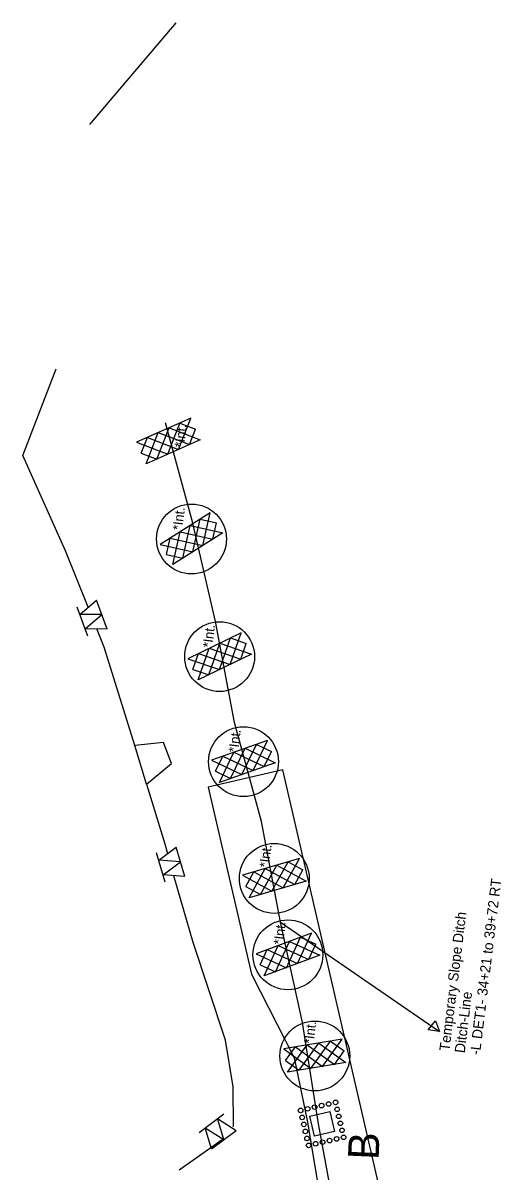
# Model space of a CAD drawing. Extents: x 400935 to 481562, y 415700 to 505362.
# Drawn here: x 481162 to 481396, y 491893 to 492453 of the extents above; entities that cross this region are included whole.
import ezdxf

# ---------------------------------------------------------------- set-up
doc = ezdxf.new("R2010")
doc.units = 0
for name, color, linetype in [('303d Impaired Stream Note CELL', 7, 'Continuous'), ('Label B Final CELL', 7, 'Continuous'), ('Old_Level_2', 7, 'Continuous'), ('Rock Inlet Sediment Trap Type B Final CELL', 7, 'Continuous'), ('Scratch_Level_3', 7, 'Continuous'), ('Scratch_Level_4', 7, 'Continuous'), ('Special Sediment Control Fence Section Both CELL', 7, 'Continuous'), ('Temporary Silt Fence Both', 7, 'Continuous'), ('Temporary Silt Fence CG', 7, 'Continuous'), ('Temporary Silt Fence Final', 7, 'Continuous')]:
    doc.layers.add(name, color=color, linetype=linetype)

msp = doc.modelspace()

# ---------------------------------------------------------------- linework, layer by layer
at = {"layer": '303d Impaired Stream Note CELL'}
msp.add_line((481194.94, 492403.56), (481237.1, 492453.11), dxfattribs=at)
at = {"layer": 'Old_Level_2'}
for p, q in [((481244.14, 492260.32), (481217.7, 492248.65)), ((481238.24, 492245.09), (481244.14, 492260.32)), ((481227.68, 492240.42), (481233.58, 492255.66)), ((481232.94, 492242.75), (481238.88, 492258)), ((481233.58, 492255.66), (481248.81, 492249.76)), ((481238.88, 492258), (481246.5, 492255.02)), ((481243.57, 492247.5), (481246.5, 492255.02)), ((481217.7, 492248.65), (481232.94, 492242.75)), ((481220.04, 492243.34), (481223.01, 492251)), ((481222.37, 492238.09), (481228.27, 492253.32)), ((481248.81, 492249.76), (481222.37, 492238.09)), ((481223.01, 492251), (481238.24, 492245.09)), ((481228.27, 492253.32), (481243.55, 492247.44)), ((481220.04, 492243.34), (481227.68, 492240.42)), ((481253.61, 492214.18), (481229.21, 492198.69)), ((481245.15, 492195.13), (481248.75, 492211.1)), ((481248.75, 492211.1), (481256.72, 492209.29)), ((481250.04, 492198.24), (481253.61, 492214.18)), ((481235.39, 492188.94), (481238.96, 492204.88)), ((481259.79, 492204.43), (481235.39, 492188.94)), ((481238.96, 492204.88), (481254.94, 492201.35)), ((481240.3, 492192.04), (481243.85, 492207.99)), ((481243.85, 492207.99), (481259.79, 492204.43)), ((481254.96, 492201.42), (481256.72, 492209.29)), ((481229.21, 492198.69), (481245.15, 492195.13)), ((481232.3, 492193.79), (481234.1, 492201.8)), ((481234.1, 492201.8), (481250.04, 492198.24)), ((481232.3, 492193.79), (481240.3, 492192.04)), ((481268.69, 492155.71), (481242.7, 492143.06)), ((481263.36, 492140.27), (481268.69, 492155.71)), ((481247.75, 492132.68), (481253.09, 492148.12)), ((481252.98, 492135.2), (481258.3, 492150.66)), ((481253.09, 492148.12), (481268.57, 492142.81)), ((481258.14, 492137.73), (481263.52, 492153.19)), ((481258.3, 492150.66), (481273.74, 492145.33)), ((481263.52, 492153.19), (481271.24, 492150.5)), ((481268.59, 492142.88), (481271.24, 492150.5)), ((481242.7, 492143.06), (481258.14, 492137.73)), ((481245.23, 492137.84), (481247.92, 492145.6)), ((481273.74, 492145.33), (481247.75, 492132.68)), ((481247.92, 492145.6), (481263.36, 492140.27)), ((481245.23, 492137.84), (481252.98, 492135.2)), ((481281.61, 492103.19), (481254.34, 492093.61)), ((481274.54, 492088.46), (481281.61, 492103.19)), ((481263.64, 492084.63), (481270.71, 492099.36)), ((481269.06, 492086.54), (481276.18, 492101.28)), ((481270.71, 492099.36), (481285.43, 492092.29)), ((481276.18, 492101.28), (481283.54, 492097.72)), ((481280.04, 492090.45), (481283.54, 492097.72)), ((481254.34, 492093.61), (481269.06, 492086.54)), ((481256.25, 492088.14), (481259.81, 492095.53)), ((481258.17, 492082.72), (481265.24, 492097.44)), ((481285.43, 492092.29), (481258.17, 492082.72)), ((481259.81, 492095.53), (481274.54, 492088.46)), ((481265.24, 492097.44), (481280.01, 492090.39)), ((481256.25, 492088.14), (481263.64, 492084.63)), ((481297.18, 492045.62), (481269.44, 492037.51)), ((481278.25, 492028.04), (481286.09, 492042.38)), ((481283.76, 492029.66), (481291.66, 492044)), ((481286.09, 492042.38), (481300.42, 492034.53)), ((481289.33, 492031.29), (481297.18, 492045.62)), ((481291.66, 492044), (481298.82, 492040.05)), ((481269.44, 492037.51), (481283.76, 492029.66)), ((481271.05, 492031.94), (481275.01, 492039.14)), ((481272.68, 492026.42), (481280.52, 492040.75)), ((481275.01, 492039.14), (481289.33, 492031.29)), ((481280.52, 492040.75), (481294.9, 492032.92)), ((481294.93, 492032.98), (481298.82, 492040.05)), ((481271.05, 492031.94), (481278.25, 492028.04)), ((481300.42, 492034.53), (481272.68, 492026.42)), ((481303.1, 492009.22), (481276.01, 491999.16)), ((481296.3, 491994.37), (481303.1, 492009.22)), ((481280.03, 491988.33), (481286.84, 492003.18)), ((481285.47, 491990.34), (481292.27, 492005.2)), ((481286.84, 492003.18), (481301.73, 491996.39)), ((481290.86, 491992.35), (481297.71, 492007.22)), ((481292.27, 492005.2), (481307.12, 491998.39)), ((481297.71, 492007.22), (481305.13, 492003.79)), ((481301.76, 491996.46), (481305.13, 492003.79)), ((481276.01, 491999.16), (481290.86, 491992.35)), ((481278.02, 491993.72), (481281.45, 492001.18)), ((481307.12, 491998.39), (481280.03, 491988.33)), ((481281.45, 492001.18), (481296.3, 491994.37)), ((481278.02, 491993.72), (481285.47, 491990.34)), ((481318.03, 491957.48), (481289.52, 491952.78)), ((481289.52, 491952.78), (481302.8, 491943.26)), ((481290.45, 491947.05), (481295.24, 491953.72)), ((481291.4, 491941.38), (481300.92, 491954.66)), ((481295.24, 491953.72), (481308.52, 491944.2)), ((481297.12, 491942.31), (481306.64, 491955.6)), ((481300.92, 491954.66), (481314.24, 491945.15)), ((481302.8, 491943.26), (481312.36, 491956.54)), ((481306.64, 491955.6), (481319.91, 491946.08)), ((481308.52, 491944.2), (481318.03, 491957.48)), ((481312.36, 491956.54), (481318.99, 491951.76)), ((481290.45, 491947.05), (481297.12, 491942.31)), ((481314.28, 491945.2), (481318.99, 491951.76)), ((481319.91, 491946.08), (481291.4, 491941.38))]:
    msp.add_line(p, q, dxfattribs=at)
for centre in [(481244.53, 492201.43), (481258.24, 492144.06), (481269.89, 492092.82), (481284.92, 492035.89), (481291.57, 491998.64), (481304.7, 491949.3)]:
    msp.add_circle(centre, 17.04, dxfattribs=at)
at = {"layer": 'Rock Inlet Sediment Trap Type B Final CELL'}
msp.add_lwpolyline([(481304.5, 491910.19), (481302.26, 491919.94), (481312.01, 491922.18), (481314.24, 491912.43)], close=True, dxfattribs=at)
for centre in [(481301.17, 491923.53), (481304.58, 491924.31), (481307.99, 491925.1), (481311.41, 491925.88), (481314.82, 491926.66), (481315.6, 491923.25), (481297.76, 491922.75), (481298.54, 491919.34), (481316.38, 491919.84), (481299.33, 491915.93), (481300.11, 491912.51), (481317.17, 491916.43), (481317.95, 491913.02), (481300.89, 491909.1), (481305.09, 491906.47), (481308.5, 491907.26), (481311.91, 491908.04), (481315.32, 491908.82), (481318.73, 491909.61), (481301.67, 491905.69)]:
    msp.add_circle(centre, 1.12, dxfattribs=at)
at = {"layer": 'Scratch_Level_3'}
for points in [[(481355.37, 491722.18), (481334.07, 491768.58), (481324.82, 491817.76), (481315.61, 491866.95), (481306.43, 491916.15), (481298.76, 491965.69), (481287.96, 492014.51), (481278.67, 492063.68), (481265.49, 492111.96), (481256.21, 492161.13), (481244.98, 492209.85), (481231.8, 492258.12)], [(481287.96, 492014.51), (481365.59, 491961.24), (481360.01, 491962.07), (481363.61, 491966.44), (481365.59, 491961.24)]]:
    msp.add_lwpolyline(points, dxfattribs=at)
at = {"layer": 'Scratch_Level_4'}
msp.add_lwpolyline([(481332.89, 491715.21), (481374.23, 491721.13), (481289.04, 492088.86), (481252.67, 492080.43), (481273.82, 491989.14), (481294.57, 491948.38), (481300.91, 491917.87), (481325.82, 491768.95)], close=True, dxfattribs=at)
at = {"layer": 'Special Sediment Control Fence Section Both CELL'}
for p, q in [((481203.3, 492157.52), (481198.18, 492171.62)), ((481193.9, 492154.11), (481188.78, 492168.21)), ((481231.69, 492033.99), (481227.48, 492048.38)), ((481241.29, 492036.8), (481237.07, 492051.19)), ((481248.26, 491911.98), (481260.24, 491921.01)), ((481254.27, 491903.99), (481266.25, 491913.02))]:
    msp.add_line(p, q, dxfattribs=at)
for points in [[(481200.74, 492164.57), (481190.06, 492164.68), (481198.18, 492171.62)], [(481203.3, 492157.52), (481192.62, 492157.63), (481200.74, 492164.57)], [(481239.18, 492044), (481228.53, 492044.79), (481237.07, 492051.19)], [(481241.29, 492036.8), (481230.64, 492037.59), (481239.18, 492044)], [(481260.26, 491908.51), (481257.24, 491918.75), (481266.25, 491913.02)], [(481254.27, 491903.99), (481251.25, 491914.24), (481260.26, 491908.51)]]:
    msp.add_lwpolyline(points, dxfattribs=at)
at = {"layer": 'Temporary Silt Fence Both'}
msp.add_line((481238.59, 491893.81), (481259.43, 491908.57), dxfattribs=at)
for points in [[(481194.07, 492168.11), (481183.06, 492195.58), (481162.29, 492242.1), (481178.5, 492284.48)], [(481216.83, 492100.74), (481201.89, 492148.61), (481198.29, 492157.58)], [(481222.59, 492081.83), (481231.44, 492052.79), (481232.82, 492048)], [(481265, 491914.72), (481264.87, 491934.28), (481261.19, 491957.03), (481245.3, 492004.68), (481235.93, 492037.2)]]:
    msp.add_lwpolyline(points, dxfattribs=at)
at = {"layer": 'Temporary Silt Fence CG'}
msp.add_lwpolyline([(481222.59, 492081.83), (481234.79, 492091.9), (481230.84, 492102.24), (481216.83, 492100.74)], dxfattribs=at)
at = {"layer": 'Temporary Silt Fence Final'}
msp.add_line((481222.59, 492081.83), (481216.83, 492100.74), dxfattribs=at)

# ---------------------------------------------------------------- texts
at = {"layer": 'Label B Final CELL'}
msp.add_text('B', height=15, rotation=87.5918, dxfattribs=at).set_placement((481335.81, 491898.42))
at = {"layer": 'Old_Level_2'}
for p in [(481240.91, 492245.93), (481239.98, 492205.47), (481254.67, 492148.24), (481267.23, 492097.14), (481282.31, 492041.01), (481289.23, 492003.39), (481304.04, 491954.89)]:
    msp.add_text('*Int.', height=4.746, rotation=83.0423, dxfattribs=at).set_placement(p)
at = {"layer": 'Scratch_Level_3'}
for s, p in [('-L DET1- 34+21 to 39+72 RT', (481385.28, 491949.61)), ('Temporary Slope Ditch', (481370.39, 491951.43)), ('Ditch-Line', (481377.84, 491950.52))]:
    msp.add_text(s, height=5, rotation=83.0365, dxfattribs=at).set_placement(p)

doc.saveas('drawing.dxf')
